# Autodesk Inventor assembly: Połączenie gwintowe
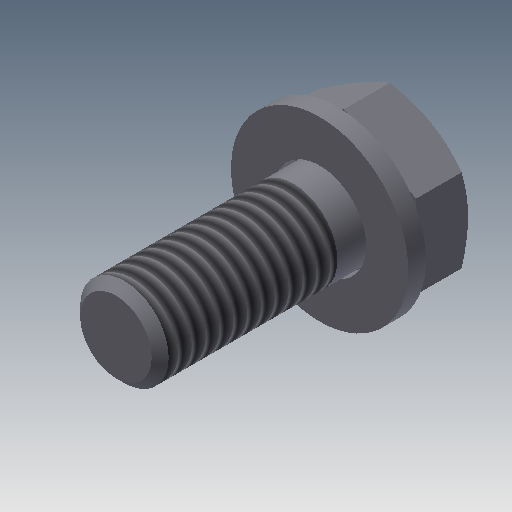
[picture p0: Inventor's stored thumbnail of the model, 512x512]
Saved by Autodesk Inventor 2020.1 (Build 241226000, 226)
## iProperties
Created: 2010-10
Part Number: Połączenie gwintowe
Document SubType Name: Assembly
Designer: F.Stasiak
ClientObjectVersion: 1
Manager: www.cadconsulting.pl
Company: Fabian Stasiak CAD Consulting
Author: F.Stasiak
Subject: Zbiór ćwiczeń. Autodesk Inventor 2020. Kurs podstawowy
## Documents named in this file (3)
- C:\2020_Kurs_podstawowy\R9 Zarządzanie plikami\369-000\Design Accelerator\Połączenie gwintowe7.iam
- C:\2020_Kurs_podstawowy\Zasoby\Content Center Files\pl-PL\ISO 7089\ISO 7089 - 8 - 140 HV(1).ipt
- C:\2020_Kurs_podstawowy\Zasoby\Content Center Files\pl-PL\ISO 4017(1)\ISO 4017 - M8 x 20ISO.ipt
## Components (2 placed, 2 different names)
1. ISO 7089 8 - 140 HV:1
2. ISO 4017 M8 x 20:1
